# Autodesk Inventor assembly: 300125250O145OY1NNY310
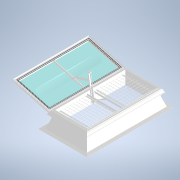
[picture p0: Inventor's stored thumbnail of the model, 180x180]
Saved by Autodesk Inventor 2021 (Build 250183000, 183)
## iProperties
Category: PARTsolutions
Company: KINGSPAN
Created: 2026-04
Part Number: 300125250O145OY1NNY310
Catalog Web Link: www.3dfindit.com
Description: LK neo plus-
Vendor: KINGSPAN
Document SubType Name: Assembly
Designer: psAdmin
Manufacturer: KINGSPAN
Mass: 590073 g
Surface Area: 253103 cm^2
Volume: 590073 cm^3
Density: 1 g/cm^3
Title: LKneoplus125250O145Y1NNY31
Author: Cadenas PARTsolutions
PSOL_IDENT_0: {$CADENAS_DATA/23d-libs/kingspan_kla/light_dome_classic_neoplus/light_dome_classic_neoplus_asmtab.pr
PSOL_IDENT_1: j},271 {VTYP=3D},{STYP=ASSTAB},{NB=300125250O145OY1NNY310},{LINA=LKneoplus125250O145Y1NNY31},{NN=LK
PSOL_IDENT_2: neo plus},{DATE=05.11.2025 13:48:11},{GEOMDATE=13.01.2025 13:06:59},{VERSION=},{LINEID=10},{WBVAR=LO
PSOL_IDENT_3: DLEVEL,L,W,TG,TS,DP,OP,OC,GCW,SD,IPM,EVADSS,SSSO,BA,INS,RT},{WBNUMERIC=W,RT}  {NB=300125250O145OY1NN
PSOL_IDENT_4: Y310},{LINA=LKneoplus125250O145Y1NNY31},{KT=DUMMY},{IDNR=},{PN=LK neo plus},{LODLEVEL=300},{L=125},{
PSOL_IDENT_5: W=250},{DRIVE=1},{WX=125,250,300},{TG=O},{TS=1},{WF=included},{DP=4},{OP=5},{OC=O},{SM=Y},{GCW=Y},{S
PSOL_IDENT_6: D=1},{IPM=N},{EVADSS=N},{SSSO=Y},{BA=3},{INS=1},{INSX='1','i - insulation','2','ih - enhanced insula
PSOL_IDENT_7: tion'},{BAX='3', 'AK50 PVC', '2', 'AK30 PVC' , '7' , 'AK30 AL/ST', '8', 'AK40 AL/ST', '9' , 'AK50 AL
PSOL_IDENT_8: /ST', '13' , 'AK30 AL/AL', '14' , 'AK40 AL/AL', '15' , 'AK50 AL/AL', '16' , 'AK50 ST-TG', '10', 'AK3
PSOL_IDENT_9: 0 ST', '11' , 'AK40 ST', '12', 'AK50 ST'},{UVD=1.2},{UVDU=calculated by excell tool},{LT=39},{GV=53}
PSOL_IDENT_10: ,{SI=24},{WFX='Y','Yes','N','No'},{OPX='5','Pneumatic - NRWG F.6 LK'},{TSX='1','PC-st 20/7 + 1 shell'
PSOL_IDENT_11: ,'2','3‐shelled','3','3‐shelled with heat‐stop coating'},{LX=1250},{XWX=2500},{ANG=9.4385},{ROT=-15}
PSOL_IDENT_12: ,{PPATH=parts/light_dome_classic_asmtpl.prj},{IBM=LKneoplus125250O145Y1NNY31},{SFX='Y','Yes','N','No'
PSOL_IDENT_13: },{DPX='3', 'Fixed','1', 'Natural ventilation'  ,'4','NSHE', '2', 'NSHEV'},{OCX='O', 'Open', 'C', 'C
PSOL_IDENT_14: losed'},{SMX='Y','Yes'},{VERPRA=1},{EVADSSX='Y', 'Yes', 'N', 'No'},{RT=0},{SDX='1', 'RSM - round bar
PSOL_IDENT_15: fall-through protection mat', '2'  , 'EAD - laser cut fall-through protection mat', '3'  , 'HDS - f
PSOL_IDENT_16: all through/hale protection and shading system'}
NB: 300125250O145OY1NNY310
NN: LK neo plus
NBSYN: $LODLEVEL.$L.$W.$TG.$TS.$DP.$OP.$OC.$GCW.$SD.$IPM.$EVADSS.$SSSO.$BA.$INS.$RT.
LINA: LKneoplus125250O145Y1NNY31
CATALOG: Light + Air
PN: LK neo plus
LODLEVEL: 300
L: 125
W: 250
TG: opal
TS: PC-st 20/7 + 1 shell
WF: included
DP: NSHE
OP: Pneumatic - NRWG F6 LK
OC: Open
GCW: Yes
SD: RSM - round bar fall-through protection mat
IPM: No
EVADSS: No
BA: AK PVC 50
INS: i - insulation
UVD: 1.2
LT: 39
GV: 53
SI: 24
RT: 0
SUPPLIER: KINGSPAN
ARTICLENO: 300125250O145OY1NNY310
BOMINFO: LKneoplus125250O145Y1NNY31
CREATOR: CADENAS GmbH
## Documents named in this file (12)
- e:\temp\worker_COMMON_226\temp\tmp_1836_46_dQXOK\format_2\300125250O145OY1NNY310.iam
- e:\temp\worker_COMMON_226\temp\tmp_1836_46_dQXOK\format_2\Light dome classic(30012525045320)_part_1_neoplus.ipt
- e:\temp\worker_COMMON_226\temp\tmp_1836_46_dQXOK\format_2\Light dome classic(3001252503Y45O)_part_2_neoplus.ipt
- e:\temp\worker_COMMON_226\temp\tmp_1836_46_dQXOK\format_2\Light dome classic(300125250)_part_8_neoplus.ipt
- e:\temp\worker_COMMON_226\temp\tmp_1836_46_dQXOK\format_2\Light dome classic(30012525045)_part_9_neoplus.ipt
- e:\temp\worker_COMMON_226\temp\tmp_1836_46_dQXOK\format_2\Light dome classic(30012525045)_part_9_sec_neoplus.ipt
- e:\temp\worker_COMMON_226\temp\tmp_1836_46_dQXOK\format_2\Light dome classic(30012525045O)_part_3_neoplus.ipt
- e:\temp\worker_COMMON_226\temp\tmp_1836_46_dQXOK\format_2\Light dome classic(300125250O3)_part_4_neoplus.ipt
- e:\temp\worker_COMMON_226\temp\tmp_1836_46_dQXOK\format_2\Light dome classic(300125250)_part_5_neoplus.ipt
- e:\temp\worker_COMMON_226\temp\tmp_1836_46_dQXOK\format_2\Light dome classic(300125250)_part_6_neoplus.ipt
- e:\temp\worker_COMMON_226\temp\tmp_1836_46_dQXOK\format_2\Light dome classic(30012525045)_part_11_neoplus.ipt
- e:\temp\worker_COMMON_226\temp\tmp_1836_46_dQXOK\format_2\Light dome classic(300125250453O)_part_10_neoplus.ipt
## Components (14 placed, 11 different names)
1. Light dome classic(30012525045320)_part_1_neoplus:1
2. Light dome classic(3001252503Y45O)_part_2_neoplus:1
3. Light dome classic(300125250)_part_8_neoplus:1
4. Light dome classic(300125250)_part_8_neoplus:2
5. Light dome classic(300125250)_part_8_neoplus:3
6. Light dome classic(300125250)_part_8_neoplus:4
7. Light dome classic(30012525045)_part_9_neoplus:1
8. Light dome classic(30012525045)_part_9_sec_neoplus:1
9. Light dome classic(30012525045O)_part_3_neoplus:1
10. Light dome classic(300125250O3)_part_4_neoplus:1
11. Light dome classic(300125250)_part_5_neoplus:1
12. Light dome classic(300125250)_part_6_neoplus:1
13. Light dome classic(30012525045)_part_11_neoplus:1
14. Light dome classic(300125250453O)_part_10_neoplus:1
